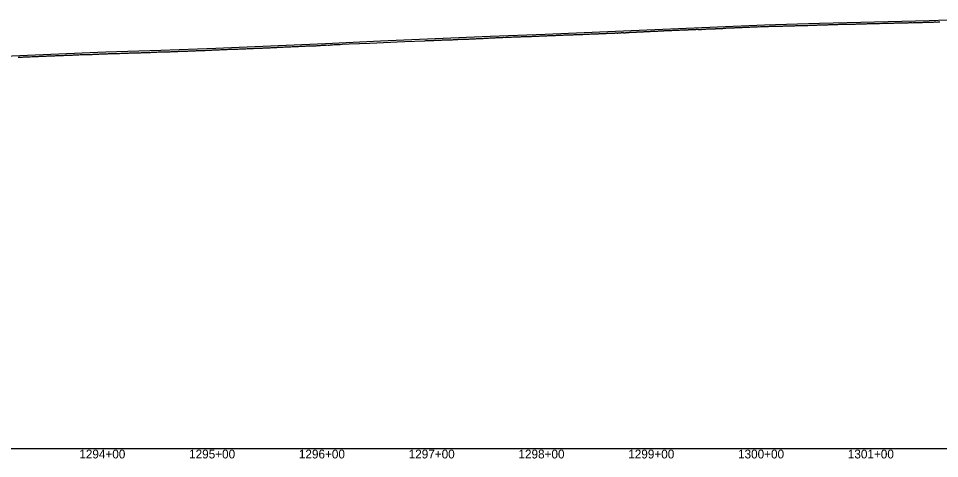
# Model space of a CAD drawing. Extents: x -3793 to 50787, y -1075 to 6138.
# Drawn here: x 16641 to 17480, y 2991 to 3392 of the extents above; entities that cross this region are included whole.
import ezdxf

# ---------------------------------------------------------------- set-up
doc = ezdxf.new("R2010")
doc.units = 0
for name, color, linetype in [('RD_DDB_Profile_EX', 7, 'Continuous'), ('RD_DDB_Profile_PR', 7, 'Continuous'), ('RD_DDB_StaTX', 7, 'Continuous'), ('RD_GPK_Profile_Cell', 7, 'Continuous')]:
    doc.layers.add(name, color=color, linetype=linetype)

msp = doc.modelspace()

# ---------------------------------------------------------------- linework, layer by layer
at = {"layer": 'RD_DDB_Profile_EX'}
for points in [[(17202.644452, 3379.06909), (17202.966006, 3379.069095), (17203.64309, 3379.170125), (17203.968629, 3379.26748), (17204.648637, 3379.335005), (17204.97445, 3379.367455), (17205.644649, 3379.367455), (17205.970949, 3379.3837), (17206.645708, 3379.38365), (17206.97358, 3379.383625), (17207.641739, 3379.41725), (17207.970103, 3379.4336), (17208.647269, 3379.46722), (17208.972933, 3379.450835), (17209.64587, 3379.450675), (17209.975555, 3379.483535), (17210.641912, 3379.550605), (17210.972092, 3379.6), (17211.642972, 3379.633455), (17211.974729, 3379.63343), (17212.648477, 3379.66688), (17212.980523, 3379.650245), (17213.644537, 3379.717085), (17213.977084, 3379.76678), (17214.645598, 3379.766675), (17214.979728, 3379.78331), (17215.646104, 3379.816755), (17215.976417, 3379.83338), (17216.644672, 3379.86665), (17216.979054, 3379.866595), (17217.645722, 3379.899735), (17217.98169, 3379.93322), (17218.641812, 3379.96644), (17218.978289, 3380), (17219.647287, 3380), (17219.984063, 3380), (17220.648338, 3380.06625), (17220.983635, 3380.066255), (17221.641922, 3380.066255), (17221.978771, 3380.1), (17222.6427, 3380.13311), (17222.979934, 3380.13314), (17223.642943, 3380.166415), (17223.981259, 3380.166425), (17224.646236, 3380.199485), (17224.980838, 3380.216325), (17225.644771, 3380.21622), (17225.981999, 3380.266855), (17226.6406, 3380.36629), (17226.977136, 3380.383175), (17227.645794, 3380.38319), (17227.981448, 3380.4), (17228.641614, 3380.433225), (17228.979627, 3380.45), (17229.644909, 3380.45), (17229.979205, 3380.45), (17230.643451, 3380.483125), (17230.980366, 3380.48316), (17231.643686, 3380.54967), (17231.978656, 3380.549765), (17232.644467, 3380.54961), (17232.979823, 3380.56647), (17233.645247, 3380.599555), (17233.982433, 3380.63316), (17234.641347, 3380.63316), (17234.977574, 3380.66681), (17235.646539, 3380.733205), (17235.981896, 3380.733235), (17236.642354, 3380.766475), (17236.977033, 3380.76654), (17237.643137, 3380.799655), (17237.9766, 3380.81644), (17238.641682, 3380.849505), (17238.980803, 3380.866345), (17239.644427, 3380.93295), (17239.97911, 3381), (17240.645209, 3381), (17240.980274, 3381), (17241.645991, 3381.0332), (17241.979829, 3380.9996), (17242.639575, 3380.999605), (17242.974978, 3381.016465), (17243.644776, 3381.08298), (17243.982349, 3381.1165), (17244.643092, 3381.149755), (17244.97749, 3381.183285), (17245.643876, 3381.183235), (17245.977051, 3381.06587), (17246.642428, 3381.09865), (17246.978208, 3381.04858), (17247.642661, 3381.082615), (17247.976547, 3381.3), (17248.643443, 3381.26674), (17248.98073, 3381.25), (17249.646733, 3381.25), (17249.980279, 3381.21643), (17250.640316, 3381.282865), (17250.975432, 3381.383505), (17251.641099, 3381.45), (17251.976589, 3381.45), (17252.646297, 3381.48324)], [(17252.646297, 3381.48324), (17252.980943, 3381.5), (17253.642107, 3381.5), (17253.977507, 3381.48325), (17254.643172, 3381.549595), (17254.978661, 3381.54969), (17255.638983, 3381.54969), (17255.973815, 3381.51631), (17256.64418, 3381.549635), (17256.978175, 3381.53313), (17257.644964, 3381.566035), (17258.140936, 3381.699355), (17258.641068, 3381.74971), (17258.97571, 3381.71636), (17259.64188, 3381.68292), (17259.975034, 3381.565585), (17260.644881, 3381.565795), (17260.982196, 3381.498955), (17261.64322, 3381.53237), (17261.977137, 3381.5997), (17262.644032, 3381.5992), (17262.976465, 3381.632715), (17263.637641, 3381.73265), (17263.974419, 3381.89987), (17264.645373, 3381.89993), (17264.976961, 3381.883255), (17265.643965, 3381.916365), (17265.977902, 3381.916535), (17266.639795, 3381.9499), (17266.975848, 3381.94996), (17267.643109, 3382.01628), (17267.97518, 3382.13329), (17268.646124, 3382.13331), (17268.979345, 3382.133345), (17269.64195, 3382.1), (17269.975675, 3381.983325), (17270.643045, 3382.049615), (17270.976618, 3382.04993), (17271.638867, 3382.083345), (17271.96995, 3382.21668), (17272.637467, 3382.249895), (17272.973894, 3382.14977), (17273.645199, 3382.183265), (17273.978061, 3382.16697), (17274.641018, 3382.167075), (17274.971395, 3382.217), (17275.639622, 3382.250005), (17275.975333, 3382.283405), (17276.642933, 3382.383025), (17276.974658, 3382.399765), (17277.640966, 3382.400385), (17277.972846, 3382.48364), (17278.641779, 3382.516845), (17278.976778, 3382.48365), (17279.645084, 3382.516705), (17279.976106, 3382.38348), (17280.638693, 3382.416975), (17280.971057, 3382.400945), (17281.643937, 3382.434685), (17282.30794, 3382.46827), (17282.971563, 3382.816575), (17283.640846, 3382.783225), (17283.972512, 3382.78316), (17284.64166, 3382.81662), (17284.974826, 3382.83328), (17285.642186, 3382.9), (17285.973021, 3382.91654), (17286.642427, 3382.98353), (17286.969616, 3382.983535), (17287.636037, 3382.983545), (17287.967505, 3382.967105), (17288.638731, 3383.00087), (17288.965681, 3383.00097), (17289.644008, 3383.001025), (17289.968334, 3383.01736), (17290.642093, 3383.051245), (17290.969453, 3383.067515), (17291.644767, 3383.067655), (17291.96607, 3383.08383), (17292.642872, 3383.1178), (17292.964267, 3383.15), (17293.643125, 3383.21801), (17293.962464, 3383.234035), (17294.643377, 3383.234105), (17294.96197, 3383.25), (17295.643896, 3383.28416), (17295.960158, 3383.3), (17296.644147, 3383.3), (17296.956819, 3383.284265), (17297.642318, 3383.318675), (17297.957828, 3383.31869), (17298.644912, 3383.35325), (17298.956007, 3383.38445), (17299.645161, 3383.41904), (17299.952687, 3383.45), (17300.643365, 3383.484595), (17300.953642, 3383.484605), (17301.645919, 3383.519355), (17301.950331, 3383.519365), (17302.644142, 3383.51951), (17302.951251, 3383.55)], [(17302.951251, 3383.55), (17303.646671, 3383.55), (17303.949413, 3383.565135), (17304.946121, 3383.630115), (17305.640527, 3383.665045), (17305.943614, 3383.66504), (17306.940317, 3383.71496), (17307.938471, 3383.8), (17308.937863, 3383.805595), (17309.936008, 3383.870605), (17310.934153, 3383.870815), (17311.933518, 3383.885465), (17312.931654, 3383.90671), (17313.92841, 3383.913895), (17314.929128, 3384.085735), (17315.925893, 3384.071625), (17316.92403, 3384.1), (17317.931188, 3384.15), (17318.927981, 3384.136025), (17319.926128, 3384.1584), (17320.925434, 3384.208575), (17321.923573, 3384.2863), (17322.921711, 3384.336405), (17323.920989, 3384.336465), (17324.915612, 3384.4), (17325.912446, 3384.45), (17326.912981, 3384.48667), (17327.909823, 3384.510265), (17328.907944, 3384.40803), (17329.908422, 3384.432535), (17330.905284, 3384.50922), (17331.903395, 3384.47283), (17332.902595, 3384.5872), (17333.900697, 3384.64924), (17334.8988, 3384.611925), (17335.90368, 3384.637335), (17336.898204, 3384.650015), (17337.896316, 3384.71239), (17338.894427, 3384.71228), (17339.891507, 3384.78787), (17340.889627, 3384.82595), (17341.887748, 3384.776165), (17342.885868, 3384.802755), (17343.883989, 3384.84148), (17344.882109, 3384.93042), (17345.88023, 3384.94255), (17346.87835, 3384.881705), (17347.872764, 3384.95922), (17348.870874, 3385.02752), (17349.876001, 3385.055225), (17350.87413, 3385.0613), (17351.873312, 3385.073275), (17352.869474, 3385.11749), (17353.867612, 3385.074885), (17354.865751, 3385.065005), (17355.863889, 3385.105335), (17356.862028, 3385.18547), (17357.856354, 3385.298105), (17358.854483, 3385.298635), (17359.852611, 3385.28817), (17360.850739, 3385.319515), (17361.848867, 3385.410185), (17362.854233, 3385.43063), (17363.853324, 3385.461925), (17364.851461, 3385.503195), (17365.847874, 3385.57352), (17366.84603, 3385.546), (17367.844186, 3385.587815), (17368.838416, 3385.656825), (17369.836562, 3385.644725), (17370.834708, 3385.69536), (17371.832854, 3385.69198), (17372.831, 3385.73435), (17373.829146, 3385.7533), (17374.827292, 3385.795775), (17375.825439, 3385.78846), (17376.831883, 3385.830685), (17377.830038, 3385.84057), (17378.822668, 3385.932995), (17379.831477, 3385.925895), (17381.118772, 3386.00303), (17382.124206, 3386.043905), (17383.118476, 3386.060075), (17384.117243, 3386.071195), (17385.116009, 3386.156685), (17386.115596, 3386.173415), (17387.115765, 3386.19244), (17388.114544, 3386.27115), (17389.113324, 3386.27524), (17390.112894, 3386.33377), (17391.110422, 3386.37755), (17392.104613, 3386.3706), (17393.110715, 3386.328205), (17394.110268, 3386.40817), (17395.10905, 3386.459505), (17396.102023, 3386.503055), (17397.100812, 3386.41813), (17398.107717, 3386.351005), (17399.106512, 3386.379935), (17400.099508, 3386.47038), (17401.098309, 3386.4716)], [(17401.098309, 3386.4716), (17402.097802, 3386.472955), (17403.104047, 3386.510635), (17404.101784, 3386.599635), (17405.095879, 3386.656275), (17406.095356, 3386.66409), (17407.094159, 3386.627575), (17408.099824, 3386.677885), (17409.094915, 3386.72207), (17410.093082, 3386.74096), (17411.092261, 3386.70925), (17412.092046, 3386.79844), (17413.085462, 3386.809995), (17414.092185, 3386.82721), (17415.090382, 3386.855155), (17416.090135, 3386.85039), (17417.088347, 3386.91206), (17418.082688, 3386.940445), (17419.090023, 3386.94075), (17420.088243, 3386.96824), (17421.087371, 3387.00834), (17422.081344, 3387.037785), (17423.080451, 3387.038815), (17424.08637, 3387.039135), (17425.086024, 3387.09526), (17426.080288, 3387.13012), (17427.078535, 3387.11587), (17428.078132, 3387.19743), (17429.079281, 3387.192), (17430.078363, 3387.18831), (17431.080028, 3387.197295), (17432.07426, 3387.276075), (17433.081078, 3387.316645), (17434.082741, 3387.361515), (17435.076976, 3387.40676), (17436.082974, 3387.407005), (17437.077205, 3387.38321), (17438.083725, 3387.383705), (17439.077949, 3387.490545), (17440.079919, 3387.51168), (17441.078693, 3387.507825), (17442.080663, 3387.57151), (17443.074076, 3387.557395), (17444.081407, 3387.54353), (17445.07482, 3387.5937), (17446.076791, 3387.63574), (17447.084121, 3387.6311), (17448.077534, 3387.66702), (17449.079505, 3387.71659), (17450.078278, 3387.70331), (17451.079947, 3387.693415), (17452.073865, 3387.76715), (17453.080397, 3387.812735), (17454.07431, 3387.766555), (17455.080854, 3387.721785), (17456.074762, 3387.79542), (17457.075935, 3387.840735), (17458.074734, 3387.88188), (17459.0764, 3387.858815), (17460.07885, 3387.885195), (17461.077645, 3388), (17462.079314, 3387.995425), (17463.073221, 3388.027245), (17464.079784, 3388.027415), (17465.073686, 3388.036515), (17466.075356, 3388.05), (17467.074159, 3388.09556), (17468.075345, 3388.13652), (17469.069247, 3388.109755), (17470.075831, 3388.16006), (17471.069729, 3388.177915), (17472.071395, 3388.15984), (17473.070217, 3388.21074), (17474.077561, 3388.26532), (17475.071446, 3388.35686), (17476.078057, 3388.35291), (17477.071938, 3388.26592), (17478.070756, 3388.41248), (17479.071982, 3388.504215), (17480.070816, 3388.55)], [(17032.930131, 3372.2269), (17033.929568, 3372.16601), (17034.929763, 3372.165435), (17035.933671, 3372.232455), (17036.930667, 3372.30594), (17037.933296, 3372.28781), (17038.929298, 3372.40525), (17039.9342, 3372.428535), (17040.930199, 3372.44187), (17041.930372, 3372.595705), (17042.934291, 3372.618245), (17043.934439, 3372.64527), (17044.93047, 3372.70408), (17045.93783, 3372.67683), (17046.937968, 3372.74884), (17047.934009, 3372.76238), (17048.93544, 3372.77587), (17049.93807, 3372.761295), (17050.9407, 3372.82446), (17051.934242, 3372.888425), (17052.941604, 3372.95249), (17053.941692, 3373.04406), (17054.937777, 3373.08795), (17055.939184, 3373.08772), (17056.941807, 3373.151205), (17057.94443, 3373.20066), (17058.937973, 3373.214865), (17059.94399, 3373.250605), (17060.946606, 3373.350055), (17061.942743, 3373.407105), (17062.946731, 3373.4426), (17063.946748, 3373.46357), (17064.949372, 3373.492065), (17065.948907, 3373.6), (17066.951537, 3373.62097), (17067.951519, 3373.67086), (17068.947709, 3373.73541), (17069.95034, 3373.77665), (17070.95297, 3373.77626), (17071.952909, 3373.864805), (17072.952477, 3373.85), (17073.9551, 3373.87033), (17074.954667, 3374.07042), (17075.950901, 3374.08519), (17076.955571, 3374.07954), (17077.955128, 3374.164725), (17078.951352, 3374.185255), (17079.950894, 3374.2353), (17080.954192, 3374.3), (17081.950409, 3374.35), (17082.949949, 3374.4), (17083.94948, 3374.364615), (17084.9528, 3374.4), (17085.949004, 3374.464625), (17086.948531, 3374.514575), (17087.948051, 3374.56453), (17088.950722, 3374.593825), (17089.948945, 3374.629015), (17090.948454, 3374.67892), (17091.951132, 3374.72908), (17092.95064, 3374.764495), (17093.947499, 3374.76442), (17094.943679, 3374.83556), (17095.949682, 3374.85), (17096.947887, 3374.9), (17097.942763, 3374.92864), (17098.939632, 3375.014245), (17099.946982, 3375.064225), (17100.941846, 3375.078395), (17101.940042, 3375.092285), (17102.936931, 3375.15), (17103.938358, 3375.23595), (17104.939125, 3375.25), (17105.93732, 3375.26387), (17106.930861, 3375.227735), (17107.935678, 3375.277655), (17108.933892, 3375.363725), (17109.931221, 3375.45), (17110.934784, 3375.436295), (17111.932998, 3375.45), (17112.931211, 3375.477), (17113.926011, 3375.52694), (17114.932104, 3375.58652), (17115.930317, 3375.63662), (17116.925106, 3375.68665), (17117.930021, 3375.7), (17118.923562, 3375.736695), (17119.927484, 3375.723275), (17120.928967, 3375.786605), (17121.930443, 3375.85), (17122.923985, 3375.9), (17123.927913, 3375.9), (17124.929382, 3375.98649), (17125.929571, 3376.03643), (17126.931024, 3376.0728), (17127.925846, 3376.1), (17128.933203, 3376.127105), (17129.933374, 3376.16361), (17130.9282, 3376.21358), (17131.929649, 3376.263615), (17132.931093, 3376.263645)], [(17132.931093, 3376.263645), (17133.933722, 3376.291165), (17134.92856, 3376.34108), (17135.929997, 3376.413725), (17136.931429, 3376.45874), (17137.931544, 3376.5), (17138.928903, 3376.55), (17139.930328, 3376.536165), (17140.93638, 3376.586155), (17141.936474, 3376.622205), (17142.932539, 3376.524735), (17143.936482, 3376.54633), (17144.936558, 3376.67195), (17145.939168, 3376.735895), (17146.932711, 3376.8141), (17147.936667, 3376.821695), (17148.939284, 3376.84308), (17149.939309, 3376.857145), (17150.935443, 3377), (17151.942808, 3377.06429), (17152.942822, 3377.078685), (17153.945425, 3377.07884), (17154.945406, 3377.093425), (17155.941571, 3377.143485), (17156.945561, 3377.2), (17157.945523, 3377.25), (17158.941714, 3377.33538), (17159.947688, 3377.33537), (17160.949032, 3377.4), (17161.945233, 3377.43532), (17162.945171, 3377.5), (17163.947768, 3377.5), (17164.948752, 3377.535265), (17165.94868, 3377.6), (17166.951277, 3377.6), (17167.947516, 3377.6), (17168.94884, 3377.685085), (17169.954785, 3377.72015), (17170.948328, 3377.714925), (17171.650584, 3377.78502), (17171.950925, 3377.785), (17172.651636, 3377.854835), (17172.954958, 3377.85485), (17173.948501, 3377.904855), (17174.652929, 3377.90489), (17174.954434, 3377.93494), (17175.65398, 3377.969775), (17175.95703, 3377.984865), (17176.649825, 3378.01973), (17176.952015, 3378.034895), (17177.650635, 3378.03484), (17177.954619, 3378.05), (17178.651696, 3378.119525), (17178.954462, 3378.15), (17179.64528, 3378.184765), (17179.950765, 3378.10845), (17180.650961, 3378.10852), (17180.958133, 3378.108555), (17181.654049, 3378.14294), (17181.960737, 3378.23468), (17182.649923, 3378.269365), (17182.95428, 3378.3), (17183.648695, 3378.3), (17183.955414, 3378.3), (17184.6477, 3378.36905), (17184.958011, 3378.369), (17185.648191, 3378.4037), (17185.95765, 3378.31089), (17186.649244, 3378.31041), (17186.960253, 3378.325725), (17187.650297, 3378.359715), (17187.962856, 3378.453165), (17188.646213, 3378.52195), (17188.956399, 3378.58439), (17189.644934, 3378.618675), (17189.959002, 3378.634315), (17190.650556, 3378.66865), (17190.964874, 3378.6372), (17191.646482, 3378.67151), (17191.961263, 3378.6085), (17192.647537, 3378.60802), (17192.963873, 3378.5762), (17193.648591, 3378.60976), (17193.966483, 3378.81588), (17194.644547, 3378.815875), (17194.962909, 3378.8), (17195.650142, 3378.83411), (17195.96588, 3378.83411), (17196.648816, 3378.868115), (17196.968483, 3378.9), (17197.644782, 3378.96807), (17197.964923, 3378.98401), (17198.645837, 3378.983955), (17198.967539, 3378.967865), (17199.641822, 3379.035735), (17199.964002, 3379.035635), (17200.647393, 3379.10352), (17200.96984, 3379.10337), (17201.64845, 3379.06921), (17201.972463, 3379.06908), (17202.644452, 3379.06909)], [(16758.928465, 3360.6625), (16759.924286, 3360.675035), (16760.924656, 3360.712575), (16761.932014, 3360.76256), (16762.932366, 3360.862615), (16763.929393, 3360.86261), (16764.929741, 3360.85), (16765.933584, 3360.887275), (16766.933906, 3360.95), (16767.929777, 3361.025605), (16768.931297, 3361.05), (16769.933941, 3361.07417), (16770.932198, 3361.1), (16771.934842, 3361.162895), (16772.935127, 3361.2), (16773.938988, 3361.186995), (16774.93253, 3361.25), (16775.936401, 3361.28694), (16776.936657, 3361.18442), (16777.939287, 3361.17083), (16778.934075, 3361.31317), (16779.940191, 3361.37635), (16780.941671, 3361.4), (16781.944294, 3361.463285), (16782.939093, 3361.55), (16783.942794, 3361.54702), (16784.938742, 3361.53368), (16785.937024, 3361.6105), (16786.939647, 3361.64702), (16787.93793, 3361.673705), (16788.933863, 3361.736835), (16789.937588, 3361.8), (16790.938253, 3361.797695), (16791.931795, 3361.8477), (16792.937919, 3361.84767), (16793.935076, 3361.83462), (16794.932106, 3361.82198), (16795.939466, 3361.95), (16796.933008, 3362.02403), (16797.932404, 3362.061205), (16798.93391, 3362.04814), (16799.933304, 3362.08544), (16800.933587, 3362.17406), (16801.934205, 3362.187105), (16802.931253, 3362.25), (16803.933889, 3362.3), (16804.934487, 3362.35), (16805.928028, 3362.375635), (16806.934179, 3362.412825), (16807.932436, 3362.412725), (16808.928298, 3362.462745), (16809.932136, 3362.46273), (16810.929195, 3362.512725), (16811.926245, 3362.58795), (16812.932411, 3362.66266), (16813.927144, 3362.712105), (16814.9265, 3362.787425), (16815.928043, 3362.824775), (16816.927397, 3362.787445), (16817.923231, 3362.85), (16818.928294, 3362.937465), (16819.927637, 3362.98752), (16820.921178, 3363), (16821.928533, 3362.98754), (16822.922074, 3363.05), (16823.921404, 3363.112405), (16824.926499, 3363.162365), (16825.922298, 3363.2), (16826.919368, 3363.25), (16827.923192, 3363.27473), (16828.920263, 3363.35), (16829.922928, 3363.38763), (16830.919884, 3363.425275), (16831.923823, 3363.46235), (16832.926487, 3363.47486), (16833.921134, 3363.462475), (16834.923805, 3363.512555), (16835.92314, 3363.5625), (16836.928122, 3363.55), (16837.9228, 3363.51148), (16838.928971, 3363.57408), (16839.931664, 3363.72453), (16840.926354, 3363.73722), (16841.932512, 3363.8), (16842.928397, 3363.912805), (16843.929907, 3363.92583), (16844.929254, 3363.92572), (16845.931962, 3363.987055), (16846.927879, 3364), (16847.93282, 3364.013), (16848.93793, 3364.063105), (16849.93388, 3364.163125), (16850.938797, 3364.2), (16851.934757, 3364.21318), (16852.937496, 3364.213265), (16853.935635, 3364.3), (16854.938373, 3364.31332), (16855.934367, 3364.386655), (16856.93925, 3364.38662), (16857.941989, 3364.436535), (16858.938009, 3364.573025)], [(16858.938009, 3364.573025), (16859.944108, 3364.57301), (16860.938897, 3364.586455), (16861.944169, 3364.6), (16862.943538, 3364.6272), (16863.945068, 3364.677435), (16864.947839, 3364.75), (16865.947222, 3364.81375), (16866.948739, 3364.85), (16867.944841, 3364.88611), (16868.950907, 3364.9), (16869.947017, 3364.95), (16870.94854, 3365.01404), (16871.944679, 3365.06406), (16872.950731, 3365.11407), (16873.953471, 3365.15), (16874.945683, 3365.235985), (16875.950426, 3365.25), (16876.946502, 3365.3), (16877.948709, 3365.336155), (16878.943513, 3365.377625), (16879.946252, 3365.42763), (16880.944361, 3365.5), (16881.943317, 3365.55), (16882.941455, 3365.6), (16883.944194, 3365.636385), (16884.936485, 3365.65), (16885.94134, 3365.690555), (16886.937372, 3365.740385), (16887.938866, 3365.813495), (16888.934569, 3365.85), (16889.937305, 3365.9), (16890.935482, 3365.9), (16891.934551, 3365.95), (16892.930559, 3366.013225), (16893.93549, 3366.02637), (16894.930258, 3366.063155), (16895.934038, 3366.13693), (16896.9288, 3366.18696), (16897.930311, 3366.213075), (16898.926169, 3366.23705), (16899.928899, 3366.32408), (16900.927139, 3366.38714), (16901.928657, 3366.43711), (16902.922278, 3366.53718), (16903.927307, 3366.53722), (16904.922054, 3366.574495), (16905.922462, 3366.64903), (16906.920736, 3366.63678), (16907.922261, 3366.674645), (16908.921735, 3366.699555), (16909.920985, 3366.774305), (16910.915721, 3366.724565), (16911.922006, 3366.71269), (16912.916734, 3366.812975), (16913.916008, 3366.812815), (16914.916568, 3367.012395), (16915.916921, 3367.01245), (16916.916298, 3367.1), (16917.917833, 3367.162435), (16918.91363, 3367.15), (16919.917558, 3367.225125), (16920.914539, 3367.375135), (16921.91715, 3367.462475), (16922.921061, 3367.37501), (16923.916868, 3367.374975), (16924.918393, 3367.462545), (16925.917779, 3367.587505), (16926.918107, 3367.674895), (16927.918689, 3367.72505), (16933.911443, 3367.97767), (16935.665096, 3368.05673), (16941.986914, 3368.341745), (16960.663695, 3369.129295), (16967.102709, 3369.419745), (16985.662289, 3370.20255), (16992.219524, 3370.498485), (17010.924123, 3371.28974), (17011.930231, 3371.35), (17012.925027, 3371.360315), (17013.927658, 3371.373385), (17014.927086, 3371.486745), (17015.662758, 3371.523375), (17016.398106, 3371.52352), (17016.927989, 3371.52353), (17017.928207, 3371.486705), (17018.93083, 3371.6), (17019.931528, 3371.686705), (17020.931736, 3371.75994), (17021.927707, 3371.759885), (17022.932642, 3371.81), (17023.928609, 3371.886645), (17024.928807, 3371.87318), (17025.929511, 3371.886665), (17026.932148, 3372.023175), (17027.92569, 3372.09636), (17028.931783, 3372.109745), (17029.926592, 3372.03305), (17030.932687, 3372.09281), (17031.926229, 3372.092825), (17032.930131, 3372.2269)], [(16640.438651, 3356.292605), (16641.433457, 3356.38519), (16642.435013, 3356.39254), (16643.437, 3356.35953), (16644.437705, 3356.401115), (16645.433385, 3356.496785), (16646.435381, 3356.59232), (16647.436069, 3356.59225), (16648.438051, 3356.626515), (16649.437132, 3356.65), (16650.439115, 3356.68438), (16651.43977, 3356.72637), (16652.850185, 3356.792045), (16653.844474, 3356.78412), (16654.847131, 3356.82594), (16655.852276, 3356.917985), (16656.847275, 3356.943895), (16657.850686, 3356.993445), (16658.851859, 3357.075565)], [(16658.851859, 3357.075565), (16659.846886, 3357.1), (16660.853475, 3357.158155), (16661.855403, 3357.175385), (16662.850441, 3357.258915), (16663.851588, 3357.3), (16664.855019, 3357.341655), (16665.850083, 3357.374925), (16666.855132, 3357.383315), (16667.857776, 3357.5), (16668.85211, 3357.499575), (16669.854761, 3357.540615), (16670.857412, 3357.591435), (16671.862407, 3357.6), (16672.858311, 3357.67437), (16673.860961, 3357.65689), (16674.86203, 3357.75), (16675.857154, 3357.7652), (16676.862932, 3357.81533), (16677.865568, 3357.8), (16678.860703, 3357.85876), (16679.861747, 3357.941175), (16680.865223, 3357.911135), (16681.864253, 3357.95299), (16682.865285, 3358.091115), (16683.867922, 3358.15), (16684.862309, 3358.17317), (16685.864953, 3358.181955), (16686.871461, 3358.2), (16687.865853, 3358.190995), (16688.868497, 3358.181835), (16689.869476, 3358.254265), (16690.864683, 3358.32252), (16691.868196, 3358.322335), (16692.87301, 3358.431585), (16693.868227, 3358.45922), (16694.870871, 3358.5407), (16695.872695, 3358.540655), (16696.875332, 3358.640575), (16697.868874, 3358.69058), (16698.871511, 3358.7), (16699.878871, 3358.645695), (16700.872413, 3358.68364), (16701.87505, 3358.742645), (16702.875937, 3358.76151), (16703.879478, 3358.80159), (16704.874782, 3358.791825), (16705.87565, 3358.77193), (16706.87828, 3358.801625), (16707.881847, 3358.87134), (16708.879184, 3359), (16709.881814, 3359.040105), (16710.884444, 3359.090025), (16711.887074, 3359.129895), (16712.882446, 3359.129865), (16713.88509, 3359.15), (16714.887735, 3359.22955), (16715.887531, 3359.3), (16716.882948, 3359.33968), (16717.889333, 3359.310325), (16718.891962, 3359.35), (16719.894592, 3359.429035), (16720.890042, 3359.489505), (16721.892686, 3359.47115), (16722.89533, 3359.539345), (16723.897974, 3359.539265), (16724.89246, 3359.58923), (16725.895111, 3359.61085), (16726.901447, 3359.65), (16727.90409, 3359.621865), (16728.899625, 3359.66095), (16729.902283, 3359.73897), (16730.904941, 3359.75557), (16731.905562, 3359.66065), (16732.900087, 3359.772415), (16733.902737, 3359.838715), (16734.905388, 3359.854535), (16735.911675, 3359.95), (16736.907289, 3359.95), (16737.909946, 3360), (16738.912604, 3360), (16739.908254, 3360.011565), (16740.910926, 3360.034935), (16741.912498, 3360.123495), (16742.915163, 3360.2), (16743.910865, 3360.2), (16744.917109, 3360.21185), (16745.919781, 3360.25), (16746.920262, 3360.288005), (16747.915993, 3360.31397), (16748.918665, 3360.36209), (16749.921337, 3360.4), (16750.921774, 3360.374465), (16751.918694, 3360.398905), (16752.919127, 3360.462285), (16753.926482, 3360.56227), (16754.926897, 3360.6), (16755.922687, 3360.6), (16756.924254, 3360.6), (16757.926911, 3360.637535), (16758.928465, 3360.6625)]]:
    msp.add_lwpolyline(points, dxfattribs=at)
at = {"layer": 'RD_DDB_Profile_PR'}
msp.add_lwpolyline([(16620.37, 3357.0255), (16670.37, 3359.1665), (16720.37, 3361.0575), (16770.37, 3362.6855), (16820.37, 3364.593), (16870.37, 3366.577), (16920.37, 3368.8925), (16970.37, 3371.1575), (17020.37, 3373.3185), (17070.37, 3375.3765), (17120.37, 3377.351), (17170.37, 3379.318), (17220.37, 3381.638), (17270.37, 3383.622), (17320.37, 3385.7805), (17370.37, 3387.2715), (17420.37, 3388.5795), (17470.37, 3389.7655), (17520.37, 3391.582)], dxfattribs=at)
at = {"layer": 'RD_GPK_Profile_Cell'}
msp.add_line((1000, 3000), (46549.603806, 3000), dxfattribs=at)

# ---------------------------------------------------------------- texts
at = {"layer": 'RD_DDB_StaTX'}
for s, p in [('1294+00', (16696.161484, 2991)), ('1294+00', (16696.165471, 2991)), ('1295+00', (16796.161484, 2991)), ('1295+00', (16796.165471, 2991)), ('1296+00', (16896.161484, 2991)), ('1296+00', (16896.165471, 2991)), ('1297+00', (16996.161484, 2991)), ('1297+00', (16996.165471, 2991)), ('1298+00', (17096.161484, 2991)), ('1298+00', (17096.165471, 2991)), ('1299+00', (17196.161484, 2991)), ('1299+00', (17196.165471, 2991)), ('1300+00', (17296.161484, 2991)), ('1300+00', (17296.165471, 2991)), ('1301+00', (17396.161484, 2991)), ('1301+00', (17396.165471, 2991))]:
    msp.add_text(s, height=8, dxfattribs=at).set_placement(p)

doc.saveas('drawing.dxf')
